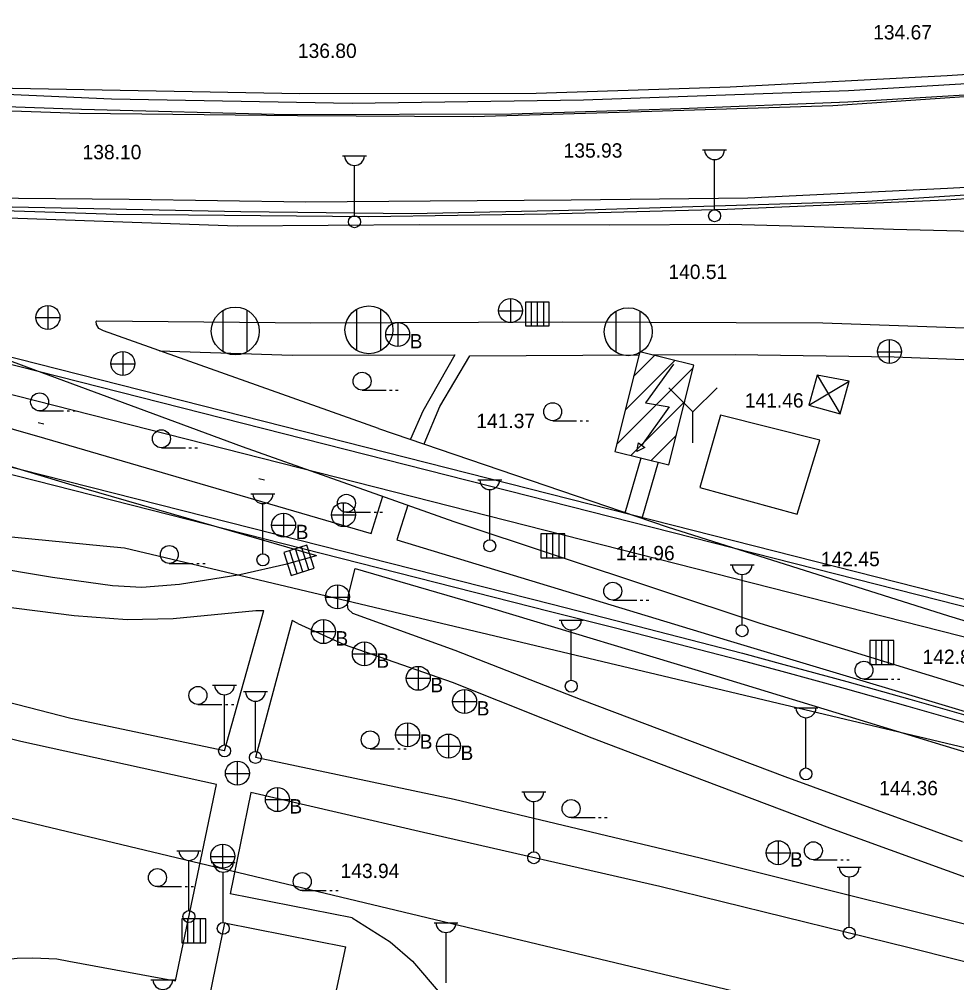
# Model space of a CAD drawing. Extents: x 419101 to 420177, y 4451541 to 4452254.
# Drawn here: x 419412.3 to 419490.6, y 4451934.1 to 4452014.6 of the extents above; entities that cross this region are included whole.
import ezdxf

# ---------------------------------------------------------------- set-up
doc = ezdxf.new("R2010")
doc.units = 0
for name, color, linetype in [('2_KADASTRO', 7, 'Continuous'), ('3_HALİHAZIR', 7, 'Continuous'), ('Level 53', 7, 'Continuous'), ('Level 60', 7, 'Continuous')]:
    doc.layers.add(name, color=color, linetype=linetype)

msp = doc.modelspace()

# ---------------------------------------------------------------- linework, layer by layer
at = {"layer": '2_KADASTRO'}
msp.add_lwpolyline([(419201.623, 4451892.026), (419189.126, 4451898.228), (419208.249, 4451935.356), (419207.935, 4451941.924), (419215.464, 4451962.72), (419225.004, 4451987.705), (419233.516, 4452012.358), (419242.834, 4452009.952), (419261.302, 4452004.943), (419280.078, 4452000.79), (419303.082, 4451996.459), (419328.791, 4451991.577), (419337.149, 4451989.99), (419348.324, 4451987.305), (419374.392, 4451980.56), (419384.764, 4451977.877), (419400.018, 4451972.489), (419419.332, 4451970.621), (419421.105, 4451970.45), (419483.513, 4451955.617), (419517.717, 4451947.488)], dxfattribs=at)
at = {"layer": '3_HALİHAZIR'}
for p, q in [((419439.314, 4452003.16), (419441.314, 4452003.16)), ((419469.371, 4452003.655), (419471.371, 4452003.655)), ((419440.314, 4451998.16), (419440.314, 4452002.353)), ((419470.371, 4451998.655), (419470.371, 4452002.848)), ((419453.353, 4451989.233), (419453.353, 4451991.233)), ((419414.739, 4451988.664), (419414.739, 4451990.664)), ((419429.361, 4451986.807), (419429.361, 4451990.267)), ((419431.361, 4451986.807), (419431.361, 4451990.267)), ((419440.514, 4451986.906), (419440.514, 4451990.366)), ((419442.514, 4451986.906), (419442.514, 4451990.366)), ((419456.575, 4451990.956), (419454.575, 4451990.956)), ((419454.575, 4451990.956), (419454.575, 4451988.956)), ((419456.575, 4451990.956), (419454.575, 4451990.956)), ((419454.575, 4451990.956), (419454.575, 4451988.956)), ((419455.079, 4451988.956), (419455.079, 4451990.956)), ((419455.575, 4451988.956), (419455.575, 4451990.956)), ((419456.122, 4451988.956), (419456.122, 4451990.956)), ((419456.575, 4451988.956), (419456.575, 4451990.956)), ((419456.575, 4451988.956), (419456.575, 4451990.956)), ((419413.719, 4451989.654), (419415.719, 4451989.654)), ((419452.333, 4451990.223), (419454.333, 4451990.223)), ((419462.161, 4451986.744), (419462.161, 4451990.204)), ((419464.161, 4451986.744), (419464.161, 4451990.204)), ((419443.917, 4451989.25), (419443.917, 4451987.25)), ((419454.575, 4451988.956), (419456.575, 4451988.956)), ((419454.575, 4451988.956), (419456.575, 4451988.956)), ((419442.917, 4451988.25), (419444.917, 4451988.25)), ((419484.98, 4451985.822), (419484.98, 4451987.822)), ((419420.989, 4451984.822), (419420.989, 4451986.822)), ((419463.613, 4451984.747), (419465.366, 4451986.5)), ((419483.96, 4451986.812), (419485.96, 4451986.812)), ((419419.969, 4451985.812), (419421.969, 4451985.812)), ((419462.198, 4451979.09), (419468.599, 4451985.49)), ((419462.905, 4451981.919), (419467.063, 4451986.076)), ((419478.937, 4451984.849), (419480.856, 4451981.613)), ((419478.239, 4451982.343), (419481.604, 4451984.341)), ((419440.946, 4451983.6), (419442.946, 4451983.6)), ((419443.246, 4451983.6), (419443.446, 4451983.6)), ((419443.746, 4451983.6), (419443.946, 4451983.6)), ((419468.565, 4451981.791), (419466.565, 4451983.791)), ((419468.565, 4451981.791), (419470.575, 4451983.791)), ((419463.386, 4451978.158), (419467.891, 4451982.662)), ((419414.031, 4451981.874), (419416.031, 4451981.874)), ((419416.331, 4451981.874), (419416.531, 4451981.874)), ((419416.831, 4451981.874), (419417.031, 4451981.874)), ((419468.565, 4451979.201), (419468.565, 4451981.791)), ((419456.855, 4451981.054), (419458.855, 4451981.054)), ((419459.155, 4451981.054), (419459.355, 4451981.054)), ((419459.655, 4451981.054), (419459.855, 4451981.054)), ((419465.083, 4451977.733), (419467.183, 4451979.833)), ((419424.194, 4451978.793), (419426.194, 4451978.793)), ((419426.494, 4451978.793), (419426.694, 4451978.793)), ((419426.994, 4451978.793), (419427.194, 4451978.793)), ((419450.602, 4451976.114), (419452.602, 4451976.114)), ((419451.602, 4451971.114), (419451.602, 4451975.307)), ((419431.671, 4451974.94), (419433.671, 4451974.94)), ((419439.403, 4451972.201), (419439.403, 4451974.201)), ((419432.671, 4451969.94), (419432.671, 4451974.133)), ((419439.641, 4451973.408), (419441.641, 4451973.408)), ((419441.941, 4451973.408), (419442.141, 4451973.408)), ((419442.441, 4451973.408), (419442.641, 4451973.408)), ((419434.397, 4451973.331), (419434.397, 4451971.331)), ((419438.383, 4451973.191), (419440.383, 4451973.191)), ((419433.397, 4451972.331), (419435.397, 4451972.331)), ((419457.857, 4451971.603), (419455.857, 4451971.603)), ((419455.857, 4451971.603), (419455.857, 4451969.603)), ((419457.857, 4451971.603), (419455.857, 4451971.603)), ((419455.857, 4451971.603), (419455.857, 4451969.603)), ((419456.361, 4451969.603), (419456.361, 4451971.603)), ((419456.857, 4451969.603), (419456.857, 4451971.603)), ((419457.404, 4451969.603), (419457.404, 4451971.603)), ((419457.857, 4451969.603), (419457.857, 4451971.603)), ((419457.857, 4451969.603), (419457.857, 4451971.603)), ((419436.329, 4451970.658), (419434.424, 4451970.048)), ((419436.329, 4451970.658), (419434.424, 4451970.048)), ((419435.515, 4451968.297), (419434.905, 4451970.202)), ((419435.987, 4451968.448), (419435.377, 4451970.353)), ((419436.508, 4451968.615), (419435.898, 4451970.52)), ((419436.939, 4451968.753), (419436.329, 4451970.658)), ((419436.939, 4451968.753), (419436.329, 4451970.658)), ((419434.424, 4451970.048), (419435.034, 4451968.143)), ((419434.424, 4451970.048), (419435.034, 4451968.143)), ((419455.857, 4451969.603), (419457.857, 4451969.603)), ((419455.857, 4451969.603), (419457.857, 4451969.603)), ((419424.856, 4451969.135), (419426.856, 4451969.135)), ((419427.156, 4451969.135), (419427.356, 4451969.135)), ((419427.656, 4451969.135), (419427.856, 4451969.135)), ((419435.034, 4451968.143), (419436.939, 4451968.753)), ((419435.034, 4451968.143), (419436.939, 4451968.753)), ((419471.669, 4451969.025), (419473.669, 4451969.025)), ((419472.669, 4451964.025), (419472.669, 4451968.218)), ((419438.914, 4451965.341), (419438.914, 4451967.341)), ((419437.894, 4451966.331), (419439.894, 4451966.331)), ((419461.869, 4451966.076), (419463.869, 4451966.076)), ((419464.169, 4451966.076), (419464.369, 4451966.076)), ((419464.669, 4451966.076), (419464.869, 4451966.076)), ((419437.717, 4451964.451), (419437.717, 4451962.451)), ((419457.41, 4451964.392), (419459.41, 4451964.392)), ((419436.717, 4451963.451), (419438.717, 4451963.451)), ((419458.41, 4451959.392), (419458.41, 4451963.585)), ((419441.137, 4451962.591), (419441.137, 4451960.591)), ((419485.342, 4451962.718), (419483.342, 4451962.718)), ((419483.342, 4451962.718), (419483.342, 4451960.718)), ((419485.342, 4451962.718), (419483.342, 4451962.718)), ((419483.342, 4451962.718), (419483.342, 4451960.718)), ((419483.846, 4451960.718), (419483.846, 4451962.718)), ((419484.342, 4451960.718), (419484.342, 4451962.718)), ((419484.89, 4451960.718), (419484.89, 4451962.718)), ((419485.342, 4451960.718), (419485.342, 4451962.718)), ((419485.342, 4451960.718), (419485.342, 4451962.718)), ((419440.137, 4451961.591), (419442.137, 4451961.591)), ((419445.638, 4451960.551), (419445.638, 4451958.551)), ((419483.342, 4451960.718), (419485.342, 4451960.718)), ((419483.342, 4451960.718), (419485.342, 4451960.718)), ((419428.47, 4451958.989), (419430.47, 4451958.989)), ((419444.638, 4451959.551), (419446.638, 4451959.551)), ((419482.842, 4451959.481), (419484.842, 4451959.481)), ((419485.142, 4451959.481), (419485.342, 4451959.481)), ((419485.642, 4451959.481), (419485.842, 4451959.481)), ((419429.47, 4451953.989), (419429.47, 4451958.182)), ((419431.044, 4451958.446), (419433.044, 4451958.446)), ((419449.507, 4451958.611), (419449.507, 4451956.611)), ((419427.24, 4451957.372), (419429.24, 4451957.372)), ((419429.54, 4451957.372), (419429.74, 4451957.372)), ((419430.04, 4451957.372), (419430.24, 4451957.372)), ((419432.044, 4451953.446), (419432.044, 4451957.639)), ((419448.507, 4451957.611), (419450.507, 4451957.611)), ((419477, 4451957.075), (419479, 4451957.075)), ((419444.748, 4451955.83), (419444.748, 4451953.83)), ((419478, 4451952.074), (419478, 4451956.267)), ((419448.159, 4451954.898), (419448.159, 4451952.898)), ((419443.748, 4451954.83), (419445.748, 4451954.83)), ((419441.62, 4451953.67), (419443.62, 4451953.67)), ((419443.92, 4451953.67), (419444.12, 4451953.67)), ((419444.42, 4451953.67), (419444.62, 4451953.67)), ((419447.159, 4451953.898), (419449.159, 4451953.898)), ((419430.551, 4451950.623), (419430.551, 4451952.623)), ((419429.531, 4451951.613), (419431.531, 4451951.613)), ((419433.877, 4451950.43), (419433.877, 4451948.43)), ((419454.281, 4451950.077), (419456.281, 4451950.077)), ((419432.877, 4451949.43), (419434.877, 4451949.43)), ((419455.281, 4451945.077), (419455.281, 4451949.27)), ((419458.393, 4451947.932), (419460.393, 4451947.932)), ((419460.693, 4451947.932), (419460.893, 4451947.932)), ((419461.193, 4451947.932), (419461.393, 4451947.932)), ((419429.326, 4451943.703), (419429.326, 4451945.703)), ((419475.672, 4451945.997), (419475.672, 4451943.997)), ((419425.491, 4451945.165), (419427.491, 4451945.165)), ((419428.306, 4451944.693), (419430.306, 4451944.693)), ((419474.672, 4451944.997), (419476.672, 4451944.997)), ((419426.491, 4451940.165), (419426.491, 4451944.358)), ((419428.36, 4451944.186), (419430.36, 4451944.186)), ((419478.617, 4451944.407), (419480.617, 4451944.407)), ((419480.614, 4451943.791), (419482.614, 4451943.791)), ((419480.917, 4451944.407), (419481.117, 4451944.407)), ((419481.417, 4451944.407), (419481.617, 4451944.407)), ((419429.36, 4451939.186), (419429.36, 4451943.379)), ((419481.614, 4451938.791), (419481.614, 4451942.984)), ((419423.866, 4451942.172), (419425.866, 4451942.172)), ((419426.166, 4451942.172), (419426.366, 4451942.172)), ((419426.666, 4451942.172), (419426.866, 4451942.172)), ((419435.948, 4451941.842), (419437.948, 4451941.842)), ((419438.248, 4451941.842), (419438.448, 4451941.842)), ((419438.748, 4451941.842), (419438.948, 4451941.842)), ((419427.898, 4451939.479), (419425.898, 4451939.479)), ((419425.898, 4451939.479), (419425.898, 4451937.479)), ((419427.898, 4451939.479), (419425.898, 4451939.479)), ((419425.898, 4451939.479), (419425.898, 4451937.479)), ((419426.402, 4451937.479), (419426.402, 4451939.479)), ((419426.898, 4451937.479), (419426.898, 4451939.479)), ((419427.445, 4451937.479), (419427.445, 4451939.479)), ((419427.898, 4451937.479), (419427.898, 4451939.479)), ((419427.898, 4451937.479), (419427.898, 4451939.479)), ((419446.952, 4451939.146), (419448.952, 4451939.146)), ((419447.952, 4451934.146), (419447.952, 4451938.339)), ((419425.898, 4451937.479), (419427.898, 4451937.479)), ((419425.898, 4451937.479), (419427.898, 4451937.479)), ((419423.312, 4451934.393), (419425.312, 4451934.393))]:
    msp.add_line(p, q, dxfattribs=at)
for points in [[(419369.777, 4452010.611), (419370.696, 4452010.793), (419371.575, 4452010.8), (419385.99, 4452010.145), (419410.227, 4452008.837), (419435.753, 4452008.369), (419455.474, 4452008.382), (419471.678, 4452008.927), (419489.791, 4452009.853), (419506.52, 4452010.945), (419523.395, 4452012.32)], [(419523.557, 4452010.663), (419498.699, 4452008.665), (419481.496, 4452007.623), (419467.561, 4452007.094), (419453.416, 4452006.642), (419434.695, 4452006.58), (419417.534, 4452007.014), (419397.166, 4452007.76), (419379.852, 4452008.938), (419371.305, 4452009.418), (419370.838, 4452009.661), (419370.721, 4452009.876), (419370.745, 4452010.121), (419370.999, 4452010.377), (419371.708, 4452010.584), (419392.39, 4452009.142), (419420.021, 4452007.921), (419440.118, 4452007.552), (419459.426, 4452007.842), (419481.56, 4452008.606), (419500.311, 4452009.723), (419523.475, 4452011.499)], [(419523.575, 4452010.477), (419506.768, 4452009.123), (419495.304, 4452008.358), (419480.228, 4452007.319), (419463.358, 4452006.812), (419450.216, 4452006.416), (419435.542, 4452006.49), (419417.355, 4452006.693), (419398.795, 4452007.329), (419384.128, 4452008.301), (419374.374, 4452009.031), (419370.784, 4452009.478), (419369.703, 4452009.776)], [(419369.012, 4452001.934), (419371.538, 4452001.785), (419390.751, 4452000.637), (419412.252, 4451999.612), (419421.496, 4451999.55), (419436.253, 4451999.316), (419446.625, 4451999.395), (419458.403, 4451999.482), (419473.154, 4451999.653), (419489.803, 4452000.449), (419506.65, 4452001.379), (419524.304, 4452003.011)], [(419370.725, 4452001.177), (419391.138, 4451999.865), (419411.739, 4451998.905), (419430.812, 4451998.509), (419445.075, 4451998.353), (419459.487, 4451998.662), (419483.093, 4451999.378), (419502.548, 4452000.628), (419515.972, 4452001.685), (419524.355, 4452002.496)], [(419524.4, 4452002.035), (419511.225, 4452000.861), (419489.663, 4451999.457), (419471.426, 4451998.665), (419456.352, 4451998.288), (419441.483, 4451998.062), (419420.436, 4451998.275), (419399.938, 4451998.918), (419380.326, 4452000.093), (419370.6, 4452000.734), (419370.558, 4452000.802), (419370.458, 4452001.231), (419370.508, 4452001.408), (419370.69, 4452001.536)], [(419520.228, 4451996.53), (419517.858, 4451996.007), (419515.991, 4451995.82), (419506.356, 4451996.209), (419494.215, 4451996.783), (419485.313, 4451997.01), (419477.853, 4451997.261), (419471.603, 4451997.422), (419461.622, 4451997.366), (419445.705, 4451997.39), (419430.505, 4451997.287), (419408.213, 4451998.056), (419389.997, 4451998.803), (419368.852, 4452000.123)], [(419442.322, 4451980.408), (419419.364, 4451988.55), (419418.966, 4451988.738), (419418.783, 4451989.077), (419418.737, 4451989.342), (419418.791, 4451989.375), (419436.661, 4451989.22), (419457.678, 4451989.3), (419479.41, 4451989.217), (419495.987, 4451988.629), (419511.418, 4451987.813), (419516.727, 4451987.734), (419523.385, 4451987.771), (419525.405, 4451987.97), (419532.105, 4451989.531), (419541.935, 4451992.712), (419560.733, 4451998.348), (419563.233, 4451998.813), (419565.397, 4451999.131), (419566.537, 4451999.183), (419567.633, 4451998.921), (419568.652, 4451998.433), (419570.322, 4451997.381)], [(419368.166, 4451992.183), (419384.8, 4451990.821), (419397.024, 4451990.215), (419400.536, 4451990.036), (419401.497, 4451989.813), (419412.931, 4451985.54), (419430.945, 4451978.903)], [(419409.262, 4451986.911), (419398.615, 4451987.648), (419401.253, 4451983.485), (419401.517, 4451983.298), (419414.433, 4451979.598), (419441.708, 4451971.639), (419442.668, 4451974.746)], [(419424.027, 4451986.896), (419435.121, 4451986.527), (419448.689, 4451986.55), (419446.025, 4451981.841), (419444.982, 4451979.5)], [(419446.122, 4451979.11), (419447.442, 4451982.249), (419449.936, 4451986.472), (419464.062, 4451986.544)], [(419465.169, 4451986.55), (419472.081, 4451986.585)], [(419472.081, 4451986.585), (419485.351, 4451986.372), (419499.888, 4451985.827)], [(419466.955, 4451985.779), (419464.612, 4451982.534), (419466.585, 4451982.212), (419464.266, 4451978.993)], [(419396.741, 4451981.468), (419397.018, 4451981.422), (419403.192, 4451979.752), (419416.44, 4451975.778), (419437.13, 4451969.803)], [(419442.322, 4451980.408), (419466.404, 4451972.181), (419489.904, 4451964.754), (419510.974, 4451958.389), (419530.845, 4451952.329), (419561.901, 4451943.145), (419581.509, 4451937.295), (419584.7, 4451936.255), (419585.825, 4451935.683), (419587.144, 4451934.881), (419588.037, 4451934.003), (419589.012, 4451932.898), (419590.121, 4451931.006), (419590.456, 4451930.189), (419590.89, 4451928.162), (419590.749, 4451926.331)], [(419430.945, 4451978.903), (419448.613, 4451972.639), (419474.144, 4451964.157), (419512.657, 4451952.335), (419540.21, 4451944.082), (419567.525, 4451936.127), (419581.013, 4451931.673), (419582.071, 4451931.103), (419583.368, 4451930.256), (419584.433, 4451929.102), (419584.728, 4451928.466), (419585.036, 4451927.471), (419585.091, 4451927.066), (419584.929, 4451925.768)], [(419462.91, 4451973.374), (419464.253, 4451977.941)], [(419465.653, 4451977.591), (419464.286, 4451972.904)], [(419444.764, 4451974.003), (419443.853, 4451971.098), (419471.414, 4451962.736), (419496.759, 4451955.137), (419516.026, 4451949.497), (419563.276, 4451935.347), (419577.547, 4451931.117), (419578.083, 4451931.055), (419578.755, 4451931.079), (419581.184, 4451931.581)], [(419395.81, 4451972.077), (419403.743, 4451970.132), (419409.252, 4451968.973), (419415.101, 4451967.983), (419420.108, 4451967.31), (419422.549, 4451967.167), (419425.697, 4451967.405), (419430.745, 4451968.211), (419434.675, 4451969.12), (419437.13, 4451969.803)], [(419395.719, 4451969.134), (419401.48, 4451967.645), (419410.549, 4451965.613), (419416.917, 4451964.786), (419421.348, 4451964.468), (419425.185, 4451964.55), (419432.066, 4451965.209), (419432.716, 4451965.212), (419432.757, 4451965.202)], [(419491.075, 4451945.926), (419476.251, 4451951.326), (419459.319, 4451957.727), (419448.709, 4451961.863), (419440.184, 4451964.954), (419439.772, 4451965.323), (419439.717, 4451965.748), (419439.806, 4451966.525), (419440.38, 4451968.725)], [(419440.38, 4451968.725), (419451.759, 4451965.394), (419470.209, 4451959.851), (419488.789, 4451954.17), (419507.792, 4451948.409), (419527.047, 4451942.885), (419545.496, 4451937.298), (419570.539, 4451929.819), (419581.437, 4451926.67), (419581.944, 4451924.914), (419580.185, 4451917.137)], [(419429.47, 4451953.489), (419432.757, 4451965.202)], [(419435.574, 4451964.141), (419435.097, 4451964.364), (419432.044, 4451952.946)], [(419435.574, 4451964.141), (419439.453, 4451962.378), (419448.468, 4451959.226), (419460.131, 4451954.579), (419469.494, 4451951.035), (419479.966, 4451947.076), (419492.329, 4451942.586)], [(419429.47, 4451953.489), (419416.648, 4451956.193), (419397.061, 4451961.233), (419395.446, 4451961.627)], [(419405.721, 4451934.342), (419406.692, 4451934.845), (419408.58, 4451935.537), (419410.866, 4451936.07), (419412.156, 4451936.198), (419413.476, 4451936.213), (419415.465, 4451936.14), (419416.477, 4451935.952), (419425.371, 4451934.291), (419428.789, 4451950.694), (419412.449, 4451954.291), (419396.355, 4451958.325)], [(419498.367, 4451937.263), (419469.18, 4451944.54), (419448.634, 4451949.448), (419432.044, 4451952.946)], [(419502.299, 4451933.114), (419486.607, 4451937.063), (419465.813, 4451942.177), (419446.075, 4451946.675), (419431.661, 4451950.009), (419429.944, 4451941.562)], [(419440.11, 4451939.567), (419429.944, 4451941.562)], [(419429.452, 4451939.138), (419428.463, 4451934.272), (419426.59, 4451925.025), (419426.442, 4451924.515), (419426.489, 4451923.798), (419426.831, 4451923.273), (419435.973, 4451921.624), (419436.223, 4451921.773), (419436.44, 4451922.348), (419436.557, 4451923.065), (419439.586, 4451937.131)], [(419429.452, 4451939.138), (419439.586, 4451937.131)], [(419440.11, 4451939.567), (419443.293, 4451937.546), (419445.147, 4451935.946), (419447.462, 4451933.258), (419449.268, 4451930.765), (419450.329, 4451928.765), (419451.772, 4451925.299), (419452.967, 4451921.729), (419453.385, 4451919.928), (419453.512, 4451918.09), (419453.529, 4451913.193), (419462.181, 4451913.328), (419465.752, 4451913.172), (419469.965, 4451912.796), (419473.259, 4451912.291), (419476.541, 4451911.407), (419480.903, 4451909.975), (419484.885, 4451908.555), (419496.201, 4451904.113)]]:
    msp.add_lwpolyline(points, dxfattribs=at)
for points in [[(419464.129, 4451986.81), (419462.048, 4451978.492), (419466.565, 4451977.363), (419468.646, 4451985.68)], [(419478.937, 4451984.849), (419478.239, 4451982.343), (419480.856, 4451981.613), (419481.604, 4451984.341)], [(419469.126, 4451975.471), (419477.266, 4451973.248), (419479.162, 4451979.429), (419470.863, 4451981.523)], [(419464.007, 4451979.208), (419464.543, 4451978.827), (419463.89, 4451978.487), (419463.961, 4451978.922)]]:
    msp.add_lwpolyline(points, close=True, dxfattribs=at)
for centre, radius in [((419470.371, 4451998.155), 0.5), ((419440.314, 4451997.66), 0.5), ((419453.338, 4451990.241), 1), ((419414.724, 4451989.673), 1), ((419430.361, 4451988.537), 2), ((419441.514, 4451988.636), 2), ((419463.161, 4451988.474), 2), ((419443.917, 4451988.25), 1), ((419484.965, 4451986.83), 1), ((419420.974, 4451985.83), 1), ((419440.946, 4451984.35), 0.75), ((419414.031, 4451982.624), 0.75), ((419456.855, 4451981.804), 0.75), ((419424.194, 4451979.543), 0.75), ((419439.388, 4451973.209), 1), ((419439.641, 4451974.158), 0.75), ((419434.397, 4451972.331), 1), ((419451.602, 4451970.614), 0.5), ((419424.856, 4451969.885), 0.75), ((419432.671, 4451969.44), 0.5), ((419438.899, 4451966.349), 1), ((419461.869, 4451966.826), 0.75), ((419437.717, 4451963.451), 1), ((419472.669, 4451963.525), 0.5), ((419441.137, 4451961.591), 1), ((419445.638, 4451959.551), 1), ((419482.842, 4451960.231), 0.75), ((419458.41, 4451958.892), 0.5), ((419427.24, 4451958.122), 0.75), ((419449.507, 4451957.611), 1), ((419444.748, 4451954.83), 1), ((419441.62, 4451954.42), 0.75), ((419448.159, 4451953.898), 1), ((419429.47, 4451953.489), 0.5), ((419432.044, 4451952.946), 0.5), ((419430.536, 4451951.631), 1), ((419478, 4451951.574), 0.5), ((419433.877, 4451949.43), 1), ((419458.393, 4451948.682), 0.75), ((419429.311, 4451944.711), 1), ((419475.672, 4451944.997), 1), ((419478.617, 4451945.157), 0.75), ((419455.281, 4451944.577), 0.5), ((419423.866, 4451942.922), 0.75), ((419435.948, 4451942.592), 0.75), ((419426.491, 4451939.665), 0.5), ((419429.36, 4451938.686), 0.5), ((419481.614, 4451938.291), 0.5)]:
    msp.add_circle(centre, radius, dxfattribs=at)
for centre in [(419440.314, 4452003.19), (419470.371, 4452003.685), (419451.602, 4451976.144), (419432.671, 4451974.969), (419472.669, 4451969.054), (419458.41, 4451964.422), (419429.47, 4451959.019), (419432.044, 4451958.476), (419478, 4451957.104), (419455.281, 4451950.107), (419426.491, 4451945.195), (419429.36, 4451944.215), (419481.614, 4451943.821), (419447.952, 4451939.176), (419424.312, 4451934.423)]:
    msp.add_arc(centre, 0.837, 183.298, 356.90719, dxfattribs=at)
at = {"layer": 'Level 53'}
for p, q in [((419395.837, 4451990.398), (419562.961, 4451947.939)), ((419395.796, 4451989.791), (419562.821, 4451947.359)), ((419395.631, 4451987.31), (419562.211, 4451944.989)), ((419395.196, 4451980.763), (419456.669, 4451965.139)), ((419395.237, 4451981.37), (419456.819, 4451965.729)), ((419413.908, 4451980.91), (419414.388, 4451980.79)), ((419432.319, 4451976.23), (419432.809, 4451976.11)), ((419456.819, 4451965.729), (419462.119, 4451964.379)), ((419456.669, 4451965.139), (419461.979, 4451963.799)), ((419461.979, 4451963.799), (419467.269, 4451962.439)), ((419462.119, 4451964.379), (419467.419, 4451963.019)), ((419467.419, 4451963.019), (419472.709, 4451961.639)), ((419467.269, 4451962.439), (419472.559, 4451961.059)), ((419472.709, 4451961.639), (419476.149, 4451960.719)), ((419472.559, 4451961.059), (419475.989, 4451960.139)), ((419476.149, 4451960.719), (419481.419, 4451959.289)), ((419475.989, 4451960.139), (419481.259, 4451958.709)), ((419481.419, 4451959.289), (419486.669, 4451957.819)), ((419481.259, 4451958.709), (419486.509, 4451957.239)), ((419486.669, 4451957.819), (419491.92, 4451956.309)), ((419486.509, 4451957.239), (419491.75, 4451955.729))]:
    msp.add_line(p, q, dxfattribs=at)
at = {"layer": 'Level 60'}
msp.add_lwpolyline([(419688.986, 4452017.192), (419689.037, 4452022.571), (419759.95, 4452036.197), (419762.427, 4452036.816), (419753.757, 4452095.962), (419557.738, 4452048.273), (419399.188, 4452040.842), (419393.304, 4451952.278), (419552.472, 4451914.189), (419541.945, 4451850.398), (419587.288, 4451839.807)], dxfattribs=at)

# ---------------------------------------------------------------- texts
at = {"layer": '3_HALİHAZIR'}
for s, p in [('134.67 ', (419483.605, 4452012.87)), ('136.80 ', (419435.588, 4452011.325)), ('138.10 ', (419417.614, 4452002.873)), ('135.93 ', (419457.77, 4452003.005)), ('140.51 ', (419466.516, 4451992.877)), ('141.46 ', (419472.892, 4451982.146)), ('141.37 ', (419450.482, 4451980.433)), ('141.96 ', (419462.132, 4451969.406)), ('142.45 ', (419479.249, 4451968.91)), ('142.87 ', (419487.734, 4451960.748)), ('144.36 ', (419484.106, 4451949.79)), ('143.94 ', (419439.152, 4451942.882))]:
    msp.add_text(s, height=1.2, rotation=359.99801, dxfattribs=at).set_placement(p)
for p in [(419444.917, 4451987.088), (419435.397, 4451971.169), (419438.717, 4451962.289), (419442.137, 4451960.429), (419446.638, 4451958.389), (419450.507, 4451956.449), (419445.748, 4451953.669), (419449.159, 4451952.736), (419434.877, 4451948.269), (419476.672, 4451943.836)]:
    msp.add_text('B', height=1.2, dxfattribs=at).set_placement(p)

doc.saveas('drawing.dxf')
